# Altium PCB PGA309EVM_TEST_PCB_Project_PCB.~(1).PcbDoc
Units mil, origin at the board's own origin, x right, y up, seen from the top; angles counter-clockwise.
Board outline 6000 x 1500 mil, 2 copper layers (Top Layer, Bottom Layer), stack 62 mil thick; 95 components, 57 nets, 264 pads, 34 vias.
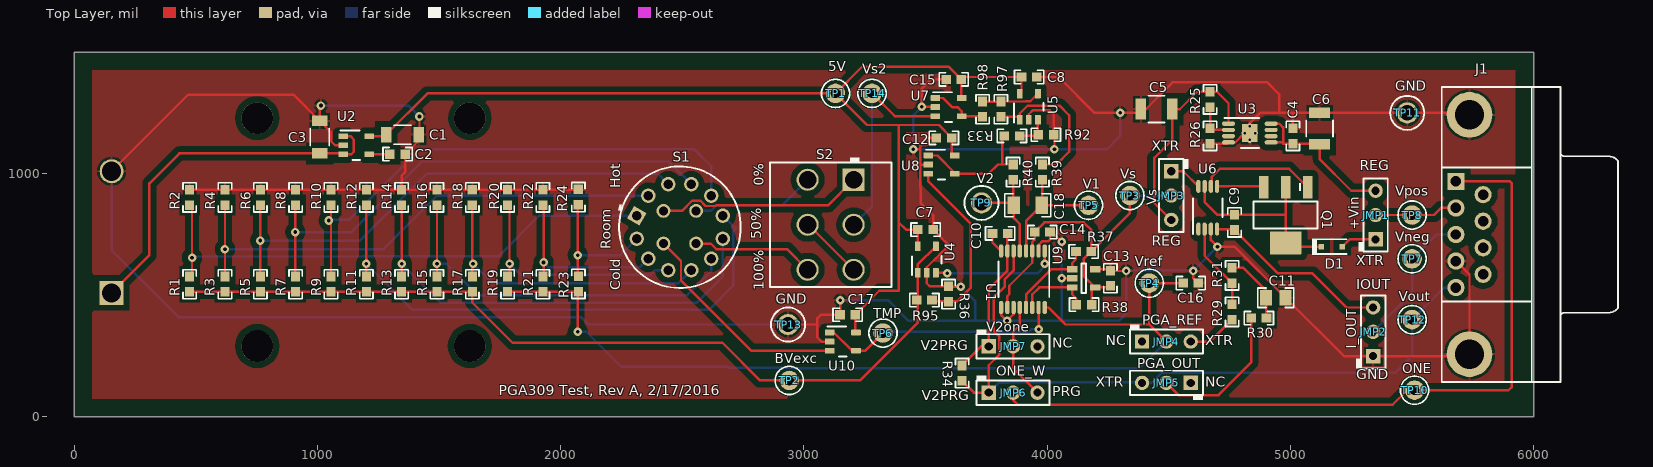
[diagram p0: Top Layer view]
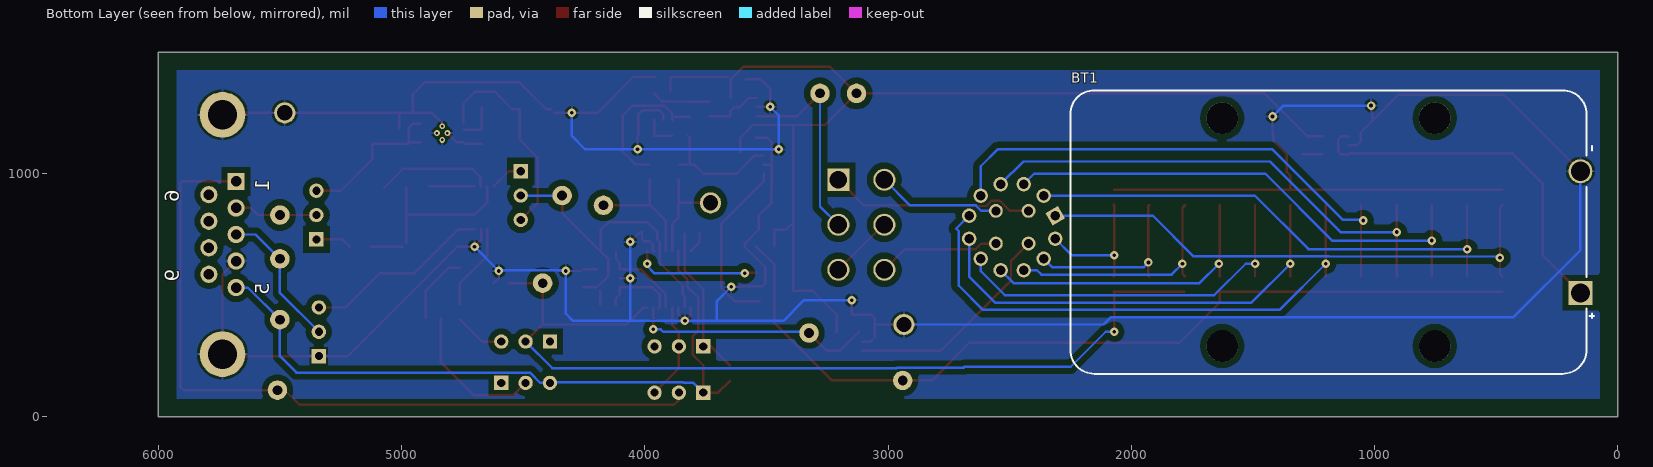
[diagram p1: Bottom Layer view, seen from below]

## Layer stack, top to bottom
Top Solder: solder mask 0.4, Solder Resist, Dk 3.5
Top Layer: signal copper 1.4
Dielectric1: core 59.2, FR-4, Dk 4.8
Bottom Layer: signal copper 1.4
Bottom Solder: solder mask 0.4, Solder Resist, Dk 3.5

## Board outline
0,0 0,1500 6000,1500 6000,0

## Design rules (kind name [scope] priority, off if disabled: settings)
AcuteAngle [All] p1: minimum=4.50000000000000E+0001 checktracksonly=FALSE
AssemblyTestPointUsage [All] p1: valid=2
BoardOutlineClearance BoardOutlineClearance_MountingHoles [OnCopper and InComponentClass('Mounting Holes')] p1: gap=40
BoardOutlineClearance BoardOutlineClearance_Poly [OnCopper and InPoly] p2: gap=25
BoardOutlineClearance [OnCopper and Not InComponentClass('Logo') and not InComponentClass('FiducialMark') and not InRegion(1000,500,4000,800)] p3: gap=75
Clearance Clearance_Keepouts [((IsTrack Or IsArc) And Not InPoly) And IsFree and IsKeepOut vs ((IsTrack Or IsArc) And Not InPoly) And IsFree and IsKeepOut] p1: gap=0
Clearance Clearance_Poly [InPolygon] p2: gap=25
Clearance [All] p3: gap=7.87
ComponentClearance ComponentClearance_MountingHoles_FiducialMarks [InComponentClass('Mounting Holes') vs InComponentClass('FiducialMark')] p1: gap=50 collisioncheckmode=3 verticalgap=10 showdistances=FALSE
ComponentClearance ComponentClearance_Shunt [InComponentClass('Header') vs InComponentClass('Shunt')] p2: gap=0 collisioncheckmode=3 verticalgap=0 showdistances=FALSE
ComponentClearance ComponentClearance_Logo [InComponentClass('Logo')] p3: gap=50 collisioncheckmode=3 verticalgap=10 showdistances=FALSE
ComponentClearance ComponentClearance_ScrewToNut [(HasFootprint('NY PMS 440 0025 PH')) vs (HasFootprint('Keystone_1902C'))] p4: gap=5 collisioncheckmode=3 verticalgap=10 showdistances=FALSE
ComponentClearance ComponentClearance_MountingHoles [InComponentClass('Mounting Holes')] p5: gap=250 collisioncheckmode=3 verticalgap=100000 showdistances=FALSE
ComponentClearance ComponentClearance_SmallPassives [HasFootprint('0201*') or HasFootprint('0402*') or HasFootprint('0508') or HasFootprint('0603*') or HasFootprint('0612') or HasFootprint('0805*') or HasFootprint('0815*') or HasFootprint('0830*') or HasFootprint('1206*') or HasFootprint('1210*') or HasFootprint('1808*') or HasFootprint('1812*') or HasFootprint('1825*') or HasFootprint('2010*') or HasFootprint('2220*') or HasFootprint('2225*') or HasFootprint('2512*') or HasFootprint('2728*') or HasFootprint('3518*') vs HasFootprint('0201*') or HasFootprint('0402*') or HasFootprint('0508') or HasFootprint('0603*') or HasFootprint('0612') or HasFootprint('0805*') or HasFootprint('0815*') or HasFootprint('0830*') or HasFootprint('1206*') or HasFootprint('1210*') or HasFootprint('1808*') or HasFootprint('1812*') or HasFootprint('1825*') or HasFootprint('2010*') or HasFootprint('2220*') or HasFootprint('2225*') or HasFootprint('2512*') or HasFootprint('2728*') or HasFootprint('3518*')] p6: gap=14.96 collisioncheckmode=3 verticalgap=10 showdistances=FALSE
ComponentClearance ComponentClearance_THtoSMT [IsThruComponent vs IsSMTComponent] p7: gap=40 collisioncheckmode=3 verticalgap=30 showdistances=FALSE
ComponentClearance ComponentClearance_THtoTH [IsThruComponent vs IsThruComponent] p8: gap=30 collisioncheckmode=3 verticalgap=30 showdistances=FALSE
ComponentClearance [All] p9: gap=30 collisioncheckmode=3 verticalgap=10 showdistances=FALSE
DiffPairsRouting [All] p1: maxlimit=100 minlimit=10 mostfreqgap=10 toplayer_minwidth=15 toplayer_maxwidth=15 toplayer_prefwidth=15 bottomlayer_minwidth=15 bottomlayer_maxwidth=15 bottomlayer_prefwidth=15 maxuncoupledlength=1000
FabricationTestPointUsage TestPointUsage [All] p1: valid=2 allowmultiple=FALSE
FabricationTestpoint Testpoint [All] p1: side=3 testpointundercomponent=TRUE minsize=40 maxsize=100 preferedsize=60 minholesize=0 maxholesize=40 preferedholesize=32 testpointgrid=1 allowsidetop=TRUE allowsidebottom=TRUE usegrid=TRUE gridtolerance=0.01
FanoutControl Fanout_LCC [IsLCC] p1: bgadir=Out bgaviamode=Centered fanoutstyle=Auto fanoutdirection=Alternating viagrid=1 // Fanout_LCC (Default Rule)
FanoutControl Fanout_BGA [IsBGA] p2: bgadir=Out bgaviamode=Centered fanoutstyle=Auto fanoutdirection=Alternating viagrid=1 // Fanout_BGA (Default Rule)
FanoutControl Fanout_Default [All] p4: bgadir=Out bgaviamode=Centered fanoutstyle=Auto fanoutdirection=Alternating viagrid=1 // Fanout_Default (Default Rule)
FanoutControl Fanout_Small [(CompPinCount < 5)] p5: bgadir=Out bgaviamode=Centered fanoutstyle=Auto fanoutdirection=OutThenIn viagrid=1 // Fanout_Small (Default Rule)
HoleSize [All] p1: absolutevalues=TRUE maxlimit=251 minlimit=7.87 maxpercent=80.000 minpercent=20.000
MinimumAnnularRing MinimumAnnularRing_ThermalPadVias [IsVia and InAnyComponent] p1: minimumring=5.91
MinimumAnnularRing [All] p2: minimumring=8
MinimumSolderMaskSliver MinimumSolderMaskSliver_Logo [InComponentClass('Logo') vs InComponentClass('Logo')] p1: minsoldermaskwidth=0.7
MinimumSolderMaskSliver [All] p2: minsoldermaskwidth=3.94
PlaneConnect [All] p1: planeconnectstyle=Relief reliefexpansion=10 reliefentries=4 reliefconductorwidth=10 reliefairgap=10
PolygonConnect [All] p1: connectstyle=Relief reliefconductorwidth=10 reliefentries=4 polygonreliefangle="90 Angle" airgapwidth=10
RoutingVias ThermalPadVias [IsVia and InAnyComponent] p1: holewidth=7.87 width=19.68 viastyle="Through Hole" minholewidth=7.87 minwidth=19.68 maxholewidth=12.99 maxwidth=23.62
RoutingVias [All] p2: holewidth=16 width=34 viastyle="Through Hole" minholewidth=7.87 minwidth=26 maxholewidth=40 maxwidth=65
SilkToBoardRegionClearance [Not ((IsComment or IsDesignator) And (Hide <> 'False')) and not InRegion(1000,500,4000,800)] p1:
SilkToSilkClearance SilkToSilkClearance_Pb-FreeLogo [(HasFootprint('Pb-Free_Overlay_Medium') OR HasFootprint('Pb-Free_Overlay_Small')) vs (HasFootprint('Pb-Free_Overlay_Medium') OR HasFootprint('Pb-Free_Overlay_Small'))] p1: silktosilkclearance=0
SilkToSilkClearance [All] p2: silktosilkclearance=4
SilkToSolderMaskClearance SilkToComponentPadClearance [IsPad and InAnycomponent] p1: minsilkscreentomaskgap=5 clearancetoexposedcopper=TRUE
SilkToSolderMaskClearance "Silk to Solder Mask Opening" [All] p2: minsilkscreentomaskgap=4 clearancetoexposedcopper=FALSE
SolderMaskExpansion [All] p1: expansion=1.97
Width [All] p1: maxlimit=100 minlimit=6 preferedwidth=10 checkconnectedcopper=TRUE
15 further rules are at their usual default settings.

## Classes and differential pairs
component class Header: JMP1 JMP2 JMP3 JMP4 JMP5 JMP6 JMP7 JMP99

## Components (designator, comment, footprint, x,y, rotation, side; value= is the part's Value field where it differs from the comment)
BT1 "1294" Keystone_1294 1190,760 r0 bottom
C1 "885012208068" 1206_190 1350,1160 r0 top
C2 "06031C103JAT2A" 0603 1330,1080 r0 top
C3 "885012208068" 1206_190 1010,1150 r90 top
C4 "C0603C104K5RACTU" 0603 5010,1155 r90 top
C5 "12103C106KAT2A" 1210_280 4450,1265 r180 top
C6 "12103C106KAT2A" 1210_280 5120,1185 r90 top
C7 "C0603C104K5RACTU" 0603 3500,770 r180 top
C8 "C0603C104K5RACTU" 0603 3925.87,1397.4 r0 top
C9 "C0603C103J5RACTU" 0603 4770,800 r270 top
C10 "06035A561JAT2A" 0603 3806.83,754.84 r0 top
C11 "08051C223JAT2A" 0805_HV 4940,490 r0 top
C12 "C0603C104K5RACTU" 0603 3575.87,1147.4 r0 top
C13 "C0603C104K5RACTU" 0603 4260.16,570 r270 top
C14 "C0603C104K5RACTU" 0603 3980,760 r180 top
C15 "C0603C104K5RACTU" 0603 3615.87,1387.4 r0 top
C16 "06033C101KAT2A" 0603 4590,550 r0 top
C17 "C0603C104K5RACTU" 0603 3180,420 r0 top
C18 "C3216C0G1E103J" 1206 3920,870 r180 top
D1 "ZHCS400TA" sod-323 5170,700 r0 top
J1 "182-009-213R171" NORCOMP_182-009-213R171 6110,750 r270 top
JMP1 "+Vin" Mill-Max_800-10-003-10-001000 5350,830 r90 top
JMP2 "I_OUT" Mill-Max_800-10-003-10-001000 5340,350 r90 top
JMP3 "Vs" Mill-Max_800-10-003-10-001000 4510,910 r270 top
JMP4 "PGA_REF" Mill-Max_800-10-003-10-001000 4490,310 r0 top
JMP5 "PGA_OUT" Mill-Max_800-10-003-10-001000 4490,140 r180 top
JMP6 "ONE_W" Mill-Max_800-10-003-10-001000 3860,100 r0 top
JMP7 "V2one" Mill-Max_800-10-003-10-001000 3860,290 r0 top
Q1 "BCP55" SOT-223 4980,830 r270 top
R1 "CRCW060328K7FKEA" 0603 475.31,545.69 r90 top
R2 "CRCW06031K05FKEA" 0603 475.24,902.39 r270 top
R3 "CRCW060340K2FKEA" 0603 620.54,545.69 r90 top
R4 "CRCW06031K50FKEA" 0603 620.47,902.39 r270 top
R5 "CRCW060371K5FKEA" 0603 765.76,545.69 r90 top
R6 "CRCW06033K74FKEA" 0603 765.7,902.39 r270 top
R7 "CRCW060310K2FKEA" 0603 910.99,545.69 r90 top
R8 "CRCW06031K91FKEA" 0603 910.92,902.39 r270 top
R9 "RT0603BRD0719K3L" 0603 1056.21,545.69 r90 top
R10 "CRCW06033K65FKEA" 0603 1056.15,902.39 r270 top
R11 "CRCW060321K5FKEA" 0603 1201.44,545.69 r90 top
R12 "CRCW06034K87FKEA" 0603 1201.38,902.39 r270 top
R13 "CRCW060311K5FKEA" 0603 1346.67,545.69 r90 top
R14 "RT0603BRD074K37L" 0603 1346.6,902.39 r270 top
R15 "CRCW060311K0FKEA" 0603 1491.89,545.69 r90 top
R16 "CRCW06034K22FKEA" 0603 1491.83,902.39 r270 top
R17 "CRCW06031K05FKEA" 0603 1637.12,545.69 r90 top
R18 "RT0603BRD0723K4L" 0603 1637.05,902.39 r270 top
R19 "CRCW060342K2FKEA" 0603 1782.35,545.69 r90 top
R20 "RT0603BRD077K96L" 0603 1782.28,902.39 r270 top
R21 "RT0603BRD076K9L" 0603 1927.57,545.69 r90 top
R22 "CRCW06031K07FKEA" 0603 1927.51,902.39 r270 top
R23 "CRCW060316K2FKEA" 0603 2072.8,546.99 r90 top
R24 "CPF0603B2K0E" 0603 2072.73,904 r270 top
R25 "CRCW0603953KFKEA" 0603 4670,1305 r90 top
R26 "RT0603BRD07291KL" 0603 4670,1155 r90 top
R29 "CRCW0603191KFKEA" 0603 4760,431.5 r90 top
R30 "CRCW060311K3FKEA" 0603 4870,405.99 r0 top
R31 "CRCW060310K0FKEA" 0603 4760,581.5 r90 top
R33 "CRCW06031K00FKEA" 0603 3855,1155 r180 top
R34 "CRCW0603100RFKEA" 0603 3650,180 r270 top
R36 "CRCW060310K0FKEA" 0603 3595,505 r270 top
R37 "CRCW060310K0FKEA" 0603 4150,680 r0 top
R38 "CRCW060310K0FKEA" 0603 4151.81,461.3 r0 top
R39 "CRCW06031K00FKEA" 0603 3980.43,1006.14 r270 top
R40 "CRCW06031K00FKEA" 0603 3860.43,1006.14 r270 top
R92 "RT0603BRD07100KL" 0603 3995,1160 r0 top
R95 "CRCW060310K0FKEA" 0603 3495,480 r180 top
R97 "CRCW06031K00FKEA" 0603 3810,1265 r270 top
R98 "RT0603BRD07100KL" 0603 3735,1265 r270 top
S1 "56P30-01-4-03N" SW_56P30-01-4-03N 2490,780 r0 top
S2 "M2024SS1G03" SW_M2024 3110,790 r270 top
TP1 "5V" Keystone5000 3130,1330 r0 top
TP2 "BVexc" Keystone5000 2940,150 r0 top
TP3 "Vs" Keystone5000 4340,910 r0 top
TP4 "Vref" Keystone5000 4420,550 r0 top
TP5 "V1" Keystone5000 4170,870 r0 top
TP6 "TMP" Keystone5004 3325,345 r0 top
TP7 "Vneg" Keystone5004 5500,650 r0 top
TP8 "Vpos" Keystone5000 5500,830 r0 top
TP9 "V2" Keystone5006 3730,880 r0 top
TP10 "ONE" Keystone5000 5510,110 r0 top
TP11 "GND" Keystone5006 5480,1250 r0 top
TP12 "Vout" Keystone5000 5500,400 r0 top
TP13 "GND" Keystone5006 2935,380 r0 top
TP14 "Vs2" Keystone5000 3280,1330 r0 top
U1 "PGA309AIPWR" PW0016A_N 3900.43,566.14 r270 top
U2 "LP2985-10DBVR" DBV0005A_N 1159.93,1116.73 r0 top
U3 "TPS7A1601DGNR" DGN0008C_N 4833,1167 r0 top
U4 "OPA333AMDBVREP" DBV0005A_N 3505.16,646.83 r90 top
U5 "OPA333AMDBVREP" DBV0005A_N 3924.45,1275.07 r90 top
U6 "XTR117AIDGKR" DGK0008A_N 4660,860 r90 top
U7 "OPA333AMDBVREP" DBV0005A_N 3594.8,1273.54 r0 top
U8 "OPA333AMDBVREP" DBV0005A_N 3565.87,1037.4 r0 top
U9 "24LC32AT-I/OT" SOT-23-5 4150.16,570 r0 top
U10 "OPA333AMDBVREP" DBV0005A_N 3160,310 r0 top

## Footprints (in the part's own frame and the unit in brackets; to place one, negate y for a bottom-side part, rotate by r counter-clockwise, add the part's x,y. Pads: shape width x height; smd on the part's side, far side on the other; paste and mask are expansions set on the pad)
0603 [mm] "0603 from SM-752 data"
  rect 1x0.95 smd: 1(-0.8,0) 2(0.8,0)
  silkscreen extent -1.52,-0.69 1.52,0.69, body extent -0.87,-0.47 0.87,0.47, height 1
0805_HV [mil] "0805 with 30mil clearance between pads"
  rect 50x63 smd: 1(-40,0) 2(40,0)
  silkscreen extent -74,-40 74,40, body extent -43,-29 43,29, height 57
1206 [mm] "1206 from SM-752 data"
  rect 1.3x1.85 smd: 1(-1.45,0) 2(1.45,0)
  silkscreen extent -2.4,-1.21 2.4,1.21, body extent -1.7,-0.9 1.7,0.9, height 1.35
1206_190 [mm] "1206_190"
  rect 1.1x1.6 smd: 1(-1.7,0) 2(1.7,0)
  silkscreen extent -0.9,-1 0.9,1, body extent -1.75,-0.95 1.75,0.95, height 1.9
1210_280 [mm] "SMD, 2-Leads, Body 3.6x2.8mm, Height 2.8mm"
  rect 1.1x2.2 smd: 1(-1.65,0) 2(1.65,0)
  silkscreen extent -0.84,-1.4 0.84,1.4, body extent -1.8,-1.4 1.8,1.4, height 2.8
DBV0005A_N [mm] "SOT23, 5-Leads, Body 2.9x1.6mm, Pitch 0.95mm, Lead Span 2.8mm, IPC Medium Density"
  rrect17% 1x0.6 smd: 1(-1.375,0.95) 2(-1.375,0) 3(-1.375,-0.95) 4(1.375,-0.95) 5(1.375,0.95)
  silkscreen extent -1.62,-1.55 0.38,1.55, body extent -1.42,-1.46 1.42,1.46, height 1.09
DGK0008A_N [mm] "TSOP, 8-Leads, Body 3x3mm, Pitch 0.65mm, IPC Medium Density"
  oval 1.35x0.45 smd: 1(-2.225,0.975) 2(-2.225,0.325) 3(-2.225,-0.325) 4(-2.225,-0.975) 5(2.225,-0.975) 6(2.225,-0.325) 7(2.225,0.325) 8(2.225,0.975)
  silkscreen extent -2.75,-1.55 0.95,1.55, body extent -2.45,-1.5 2.45,1.5, height 0.96
DGN0008C_N [mm] "TSOP, 8-Leads, Body 3x3mm, Pitch 0.65mm, Thermal Pad 1.98x1.88mm, IPC Medium Density"
  rrect100% 1.35x0.45 smd: 1(-2.225,0.975) 2(-2.225,0.325) 3(-2.225,-0.325) 4(-2.225,-0.975) 5(2.225,-0.975) 6(2.225,-0.325) 7(2.225,0.325) 8(2.225,0.975)
  rrect6% 1.6x1.918 smd: 9(0,0)
  silkscreen extent -2.65,-1.55 0.95,1.55, body extent -2.46,-1.5 2.46,1.5, height 1.1
Keystone5000 [mil] "For Keystone 500x miniature loop terminals"
  round 80 hole 40: 1(0,0)
  silkscreen extent -58,-58 58,58, body extent -49,-49 49,49, height 182
Keystone5004 [mil] "For Keystone 500x miniature loop terminals"
  round 80 hole 40: 1(0,0)
  silkscreen extent -58,-58 58,58, body extent -49,-49 49,49, height 182
Keystone5006 [mil] "Keystone Compact loops"
  round 87 hole 63: 1(0,0)
  silkscreen extent -70,-70 70,70, body extent -63,-63 62,63, height 225
Keystone_1294 [mm] "9 V Molded Battery Holder, TH"
  rect 2.5x2.5 hole 2: 1(-26.3,6.35)
  round 2.5 hole 2: 2(-26.3,-6.35)
  round 3.3 hole 3.3 unplated mask+0: MH1(-11.1,11.9) MH2(-11.1,-11.9) MH3(11.1,-11.9) MH4(11.1,11.9)
  silkscreen extent -27.75,-14.8 26.95,14.8, body extent -26.95,-14.8 26.95,14.8, height 20.3
Mill-Max_800-10-003-10-001000 [mm] "Mill-Max"
  rect 1.5x1.5 hole 0.85: 1(-2.54,0)
  round 1.5 hole 0.85: 2(0,0) 3(2.54,0)
  silkscreen extent -3.81,-1.27 3.81,1.78, body extent -3.81,-1.27 3.81,1.27, height 8.13
NORCOMP_182-009-213R171 [mm] "Connector; D Subminiature 9 Position; Right Angle"
  rect 1.8x1.8 hole 1.092: 1(-5.54,-10.92)
  round 1.8 hole 1.092: 2(-2.77,-10.92) 3(0,-10.92) 4(2.77,-10.92) 5(5.54,-10.92) 6(-4.155,-8.08) 7(-1.385,-8.08) 8(1.385,-8.08) 9(4.155,-8.08)
  round 4.76 hole 3.05: 10(-12.495,-9.5) 11(12.495,-9.5)
  silkscreen extent -15.4,-12.4 15.4,6, body extent -15.41,-12.98 15.41,6.1, height 12.55
PW0016A_N [mm] "TSOP, 16-Leads, Body 5x4.4mm, Pitch 0.65mm, IPC Medium Density"
  oval 1.4x0.45 smd: 1(-2.95,2.275) 2(-2.95,1.625) 3(-2.95,0.975) 4(-2.95,0.325) 5(-2.95,-0.325) 6(-2.95,-0.975) 7(-2.95,-1.625) 8(-2.95,-2.275) 9(2.95,-2.275) 10(2.95,-1.625) 11(2.95,-0.975) 12(2.95,-0.325) 13(2.95,0.325) 14(2.95,0.975) 15(2.95,1.625) 16(2.95,2.275)
  silkscreen extent -3.5,-2.55 1.85,2.75, body extent -3.21,-2.5 3.21,2.5, height 1
sod-323 [mm] "NXP recommended land pattern"
  rect 0.6x0.6 smd paste-0.05: 1(-1.1,0) 2(1.1,0)
  silkscreen extent -2.06,-0.86 1.53,0.86, body extent -1.3,-0.67 1.3,0.68, height 1.1
SOT-23-5 [mm] "SOT23, 5-Leads, Body 2.9x1.6mm, Pitch 0.95mm, Lead Span 2.8mm, IPC Medium Density"
  rect 1.1x0.65 smd: 1(-1.2,0.95) 2(-1.2,0) 3(-1.2,-0.95) 4(1.2,-0.95) 5(1.2,0.95)
  silkscreen extent -0.25,-1.55 0.25,1.55, body extent -1.42,-1.46 1.42,1.46, height 1.08
SOT-223 [mm] "SOT223/SC73, 4-Leads, Body 6.5x3.5mm, Pitch 2.3mm, Lead Span 7mm, IPC Medium Density"
  rrect10% 2.4x1 smd: 1(-2.9,2.3) 2(-2.9,0) 3(-2.9,-2.3)
  rrect4% 2.4x3.3 smd: 4(2.9,0)
  silkscreen extent -3.33,-3.35 1.4,3.35, body extent -3.5,-3.25 3.5,3.25, height 1.62
SW_56P30-01-4-03N [mm] "TH, 16-Leads, Dia 12.7mm"
  rect 1.5x1.5 hole 1 rot 150: 1(-4.492,1.204)
  round 1.5 hole 1: 2(-3.288,3.288) 3(-1.204,4.492) 4(1.204,4.492) 5(3.288,3.288) 6(4.492,1.204) 7(4.492,-1.204) 8(3.288,-3.288) 9(1.204,-4.492) 10(-1.204,-4.492) 11(-3.288,-3.288) 12(-4.492,-1.204)
  round 1.45 hole 0.95: C1(-1.708,1.708) C2(1.708,1.708) C3(1.708,-1.708) C4(-1.708,-1.708)
  silkscreen extent -6.47,-6.35 6.35,6.35, body extent -6.35,-6.35 6.35,6.35, height 25.45
SW_M2024 [mm] "TH, 6-Leads, Body 13x12.7 mm, Pitch 4.7mm"
  rect 2.3x2.3 hole 1.8: 1(-4.7,2.4)
  round 2.3 hole 1.8: 2(0,2.4) 3(4.7,2.4) 4(-4.7,-2.4) 5(0,-2.4) 6(4.7,-2.4)
  silkscreen extent -7,-6.35 6.5,6.35, body extent -6.5,-6.35 6.5,6.35, height 29.51

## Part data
BT1: "9 V Molded Battery Holder, TH"
C1 C3: "CAP, CERM, 4.7 µF, 25 V, +/- 10%, X7R, 1206_190"
C2: "CAP, CERM, 0.01 µF, 100 V, +/- 5%, X7R, 0603"
C4 C7 C8 C12 C13 C14 C15 C17: "CAP, CERM, 0.1 µF, 50 V, +/- 10%, X7R, 0603"
C5 C6: "CAP, CERM, 10 µF, 25 V, +/- 10%, X7R, 1210"
C9: "CAP, CERM, 0.01 µF, 50 V, +/- 5%, X7R, 0603"
C10: "CAP, CERM, 560 pF, 50 V, +/- 5%, C0G/NP0, 0603"
C11: "CAP, CERM, 0.022 µF, 100 V, +/- 5%, X7R, 0805"
C16: "CAP, CERM, 100 pF, 25 V, +/- 10%, X7R, 0603"
C18: "CAP, CERM, 0.01 µF, 25 V, +/- 5%, C0G/NP0, 1206"
D1: "Diode, Schottky, 40 V, 0.4 A, SOD-323"
J1: "CONN DB9 FEMALE R/A SOLDER TH"
JMP1 JMP2 JMP3 JMP4 JMP5 JMP6 JMP7: library part 800-10-003-10-001000, "Header, 100mil, 3x1, TH"
Q1: library part "BCP55, Fairchild Semiconductor", "Transistor, NPN, 60 V, 1.5 A, SOT-223"
R1: "RES, 28.7 k, 1%, 0.1 W, 0603"
R2 R17: "RES, 1.05 k, 1%, 0.1 W, 0603"
R3: "RES, 40.2 k, 1%, 0.1 W, 0603"
R4: "RES, 1.50 k, 1%, 0.1 W, 0603"
R5: "RES, 71.5 k, 1%, 0.1 W, 0603"
R6: "RES, 3.74 k, 1%, 0.1 W, 0603"
R7: "RES, 10.2 k, 1%, 0.1 W, 0603"
R8: "RES, 1.91 k, 1%, 0.1 W, 0603"
R9: "RES, 19.3 k, 0.1%, 0.1 W, 0603"
R10: "RES, 3.65 k, 1%, 0.1 W, 0603"
R11: "RES, 21.5 k, 1%, 0.1 W, 0603"
R12: "RES, 4.87 k, 1%, 0.1 W, 0603"
R13: "RES, 11.5 k, 1%, 0.1 W, 0603"
R14: "RES, 4.37 k, 0.1%, 0.1 W, 0603"
R15: "RES, 11.0 k, 1%, 0.1 W, 0603"
R16: "RES, 4.22 k, 1%, 0.1 W, 0603"
R18: "RES, 23.4 k, 0.1%, 0.1 W, 0603"
R19: "RES, 42.2 k, 1%, 0.1 W, 0603"
R20: "RES, 7.96 k, 0.1%, 0.1 W, 0603"
R21: "RES, 6.90 k, 0.1%, 0.1 W, 0603"
R22: "RES, 1.07 k, 1%, 0.1 W, 0603"
R23: "RES, 16.2 k, 1%, 0.1 W, 0603"
R24: "RES, 2.00 k, 0.1%, 0.063 W, 0603"
R25: "RES, 953 k, 1%, 0.1 W, 0603"
R26: "RES, 291 k, 0.1%, 0.1 W, 0603"
R29: "RES, 191 k, 1%, 0.1 W, 0603"
R30: "RES, 11.3 k, 1%, 0.1 W, 0603"
R31 R36 R37 R38 R95: "RES, 10.0 k, 1%, 0.1 W, 0603"
R33 R39 R40 R97: "RES, 1.00 k, 1%, 0.1 W, 0603"
R34: "RES, 100, 1%, 0.1 W, 0603"
R92 R98: "RES, 100 k, 0.1%, 0.1 W, 0603"
S1: "Switch, 4P3T, 4Pole, 3 Pos, 0.2 A, 115 VAC, 30 VDC, TH"
S2: "Switch, Toggle SP3T, 0.4VA, 28V, TH"
TP1 TP2 TP3 TP4 TP5 TP8 TP10 TP12 TP14: library part 5000, "Test Point, Miniature, Red, TH"
TP6 TP7: library part 5004, "Test Point, Miniature, Yellow, TH"
TP9 TP11 TP13: library part 5006, "Test Point, Compact, Black, TH"
U1: "Voltage Output Programmable Sensor Conditioner, PW0016A"
U2: "Single Output Low Noise LDO, 150 mA, Fixed 10 V Output, 2.2 to 16 V Input, with Low IQ, 5-pin SOT-23 (DBV), -40 to 125 degC, Green (RoHS & no Sb/Br)"
U3: "Single Output LDO, 100 mA, Adjustable 1.2 to 18.5 V Output, 3 to 60 V Input, with Enable and Power Good, 8-pin MSOP (DGN), -40 to 125 degC, Green (RoHS & no Sb/Br)"
U4 U5 U7 U8 U10: "Enhanced Product, Micropower CMOS Operational Amplifier Zero-Drift Series, 1.8 to 5.5 V, -55 to 125 degC, 5-pin SOT23 (DBV0005A), Green (RoHS & no Sb/Br)"
U6: "4-20mA Current-Loop Transmitter, DGK0008A"
U9: "32K I2C™ Serial EEPROM, SOT-23-5"

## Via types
v1: diameter 35, hole 15, Top Layer to Bottom Layer, 30 vias
v2: diameter 24, hole 10, Top Layer to Bottom Layer, 4 vias

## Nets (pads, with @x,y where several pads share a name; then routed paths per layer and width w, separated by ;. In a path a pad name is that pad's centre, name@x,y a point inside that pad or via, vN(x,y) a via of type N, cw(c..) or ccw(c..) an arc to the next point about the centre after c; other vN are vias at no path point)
0%: S1.C1 S2.1 | length 852.6
  Top Layer w10: S1.C1 2498.66,847.23 2540.07,888.65 2574.39,888.65 2595.98,867.05 2637.01,867.05 2639.75,869.78 3099.23,869.78 S2.1
5V: C1.1 C7.2 C8.1 C12.2 C15.2 C17.2 TP1.1 U2.5 U4.5 U5.5 U7.5 U8.5 U10.5 | length 4684.6
  Top Layer w10: U2.5 C1.1@1277.2,1154.13 ; C1.1 1453.07,1330 TP1.1 ; U10.5 3211.5,350.04 C17.2 3310,518.5 3390,518.5 3390,800 ; U4.5@3468.5,701.71 C7.2 3420,770 3390,800 ; 3607.36,1087.44 C12.2 3554.76,1200 3390,1200 ; U7.5@3647.36,1312.52 C15.2 3594.76,1440 3240,1440 TP1.1 ; C15.2@3657.36,1397.4 C8.1 U5.5@3894.37,1336.52 ; TP1.1 3260,1200 3390,1200 ; 3390,800 3390,1200
9V: BT1.1 C3.1 U2.1 U2.3 | length 1506.1
  Top Layer w10: BT1.1 310,665.43 310,960 433.07,1083.07 C3.1 U2.3@1102.06,1083.07 ; U2.3 1139.33,1079.33 1150,1090 1150,1140 1135.87,1154.13 U2.1
50%: S1.C2 S2.4 | length 511.2
  Bottom Layer w10: S1.C2 2617.19,847.23 2639.75,869.78 2910.26,869.78 S2.4
100%: S1.C3 S2.6 | length 502.9
  Top Layer w10: S1.C3 2617.19,712.77 2639.75,690.22 2930.26,690.22 S2.6
BUFTEMP: TP6.1 U1.15 U10.1 U10.4 | length 1003.5
  Top Layer w10: U10.1@3120,350 3197.4,272.6 U10.4 3252.6,272.6 TP6.1 ; U1.15 3965,449.41 v1(3965,360)
  Bottom Layer w10: TP6.1 3330,350 3925,350 3935,360 v1(3965,360)
BUFVEXC: R1.1 R3.1 R5.1 R7.1 R9.1 R11.1 R13.1 R15.1 R17.1 R95.2 TP2.1 U4.1 U4.4 | length 3611.1
  Top Layer w10: R1.1 R3.1 R5.1 R7.1 R9.1 R11.1 R13.1 R15.1 R17.1 1637.12,470.51 1802.63,305 2665,305 2820,150 TP2.1 3230,150 3468.51,388.51 3468.51,510 ; 3467.76,510.75 U4.1 3467.76,626.16 U4.4
COLD_0%: R1.2 R2.2 S1.1 | length 2196.4
  Top Layer w10: R1.2@475.24,577.25 475,577.5 485,587.5 v1(485,655) 485,860.65 475,870.65 R2.2
  Bottom Layer w10: v1@489.63,659.63 1188.05,659.63 1188.79,660.37 1213.96,660.37 1214.33,660 1333.65,660 1334.02,660.37 1359.18,660.37 1359.56,660 1478.87,660 1479.25,660.37 1504.41,660.37 1504.78,660 1627.04,660 1627.42,660.37 1652.58,660.37 1652.96,660 1745,660 1912.38,827.38 S1.1
COLD_50%: R7.2 R8.2 S1.4 | length 2088.8
  Top Layer w10: R7.2@910.92,577.25 905,583.18 910,588.18 v1(910,760) 910,859.97 905,864.97 R8.2
  Bottom Layer w10: v1(910,760) 1140,760 1430,1050 2444.21,1050 S1.4
COLD_100%: R13.2 R14.2 S1.7 | length 1880.2
  Top Layer w10: R13.2@1346.6,577.25 v1(1346.6,630) R14.2
  Bottom Layer w10: v1(1346.6,630) 1506.6,470 2560,470 2666.83,576.83 S1.7
GND: BT1.2 C1.2 C2.2 C3.2 C4.2 C5.2 C6.2 C7.1 C8.2 C11.2 C12.1 C13.1 C14.1 C15.1 C16.2 C17.1 J1.4 J1.10 J1.11 JMP2.1 R2.1 R4.1 R6.1 R8.1 R10.1 R12.1 R14.1 R16.1 R18.1 R20.1 R22.1 R24.1 R26.1 R36.1 R92.2 TP11.1 TP13.1 U1.2 U1.9 U1.11 U2.2 U3.4 U3.9 U4.2 U5.2 U6.3 U7.2 U8.2 U9.2 U9.5 U10.2 | length 16743.4
  Top Layer w10: BT1.2 469.57,1325 901.93,1325 C3.2 ; R2.1 R4.1 R6.1 R8.1 R10.1 R12.1 R14.1 ; v1@1010,1275 C3.2 ; U2.2 1073.27,1116.73 1057.48,1132.52 1057.48,1169.45 C3.2 ; C1.2 1416.93,1135.43 C2.2 1361.5,1006.5 1346.6,991.6 R14.1 ; C1.2@1420,1163.07 v1(1420,1235) ; R24.1@2071.12,933.88 R22.1 R20.1 R18.1 R16.1 R14.1 ; TP13.1 3055,380 ; U10.2 3072.63,310 3055,327.63 3055,380 ; C17.1 3070,420 3055,405 3055,380 ; C17.1@3150,421.5 v1(3150,480) ; v1(3450,1100) 3479.17,1100 ; v1(3485,1275) 3485,1350 3522.4,1387.4 C15.1 ; v1@3492.4,1275 U7.2@3539.21,1275 ; U8.2 3482.4,1037.4 3479.17,1034.17 ; C12.1 3497.4,1147.4 3479.17,1129.17 3479.17,1034.17 ; R36.1@3596.49,535 v1(3645,535) ; R36.1@3600,536.49 R36.1 3518.51,536.49 3505.16,549.84 U4.2 3505.16,615.16 3558.41,668.41 3558.53,668.41 3567.24,677.12 3567.24,677.24 3590,700 3590,711.5 C7.1 3531.5,828.5 3480,880 3480,942.16 3479.17,942.99 3479.17,1034.17 ; U1.9 3810.87,419.13 v1(3835,395) 3862.05,422.05 U1.11 ; U5.2 3924.45,1244.45 3940,1260 4010,1260 4027.36,1242.64 R92.2@4027.36,1157.4 ; C8.2 4047.6,1397.4 4195,1250 v1(4300,1250) C5.2@4370.04,1250 ; U1.2@3962.13,680 U1.2 3968.27,686.14 3968.27,709.99 3981,722.72 4004.84,722.72 4011.5,729.37 C14.1 4020,760 v1(4060,720) ; v1(4030,1100) R92.2@4030,1154.76 ; v1(4060,570) U9.2 ; U9.5 C13.1@4254.25,607.4 ; C13.1@4261.65,600 v1(4325,600) ; C5.2 4405,1265 4515,1375 4905,1375 4953.5,1326.5 4953.5,1249.96 ; v1(4600,600) 4600,571.5 C16.2 ; R26.1 4740.29,1123.5 U3.4 4772.96,1128.61 v2(4811.35,1167) ; U6.3 4672.8,727.2 v1(4700,700) 4770,700 C11.2 5220,250 JMP2.1 J1.11@5727.91,250 ; v2(4833,1194.95) 4833,1208 4874.96,1249.96 4953.5,1249.96 ; C4.2 5010,1249.96 ; J1.4 5735.98,585.04 J1.11 ; J1.10 5727.91,1250 TP11.1 C6.2 C6.2 5010,1249.96 ; 4953.5,1249.96 5010,1249.96
  Bottom Layer w10: BT1.2 154.57,685.43 429.33,410.67 2084.35,410.67 2115.02,380 TP13.1 ; v1(1015,1280) 1375,1280 v1(1420,1235) ; v1(3150,480) 3345,480 3430,395 3705,395 ; v1(3485,1275) 3450,1240 v1(3450,1100) v1(4030,1100) 4245,1100 4300,1155 v1(4300,1250) ; v1(3645,535) 3705,475 3705,395 ; v1(4060,720) v1(4060,570) 4060,395 ; v1(4700,700) 4602.87,602.87 4327.87,602.87 v1(4325,600) 4325,425 4295,395 4060,395 ; 3705,395 v1(3835,395) 4060,395
  other v2: 4833,1139.05 4854.65,1167
HOT_0%: R5.2 R6.2 S1.3 | length 2102.3
  Top Layer w10: R5.2@765.7,577.25 v1(765.7,725) R6.2
  Bottom Layer w10: v1(765.7,725) 1175,725 1450,1000 2399.45,1000 S1.3
HOT_50%: R11.2 R12.2 S1.6 | length 2240.1
  Top Layer w10: R11.2@1201.38,577.25 v1(1201.38,630) R12.2
  Bottom Layer w10: v1(1201.38,630) 1391.38,440 2610,440 2709.23,539.23 2709.23,763.45 2720,774.21 S1.6 S1.6@2666.83,823.17
HOT_100%: R17.2 R18.2 S1.9 | length 1246.2
  Top Layer w10: R17.2@1637.06,577.25 R18.2
  Bottom Layer w10: v1(1640,630) 1720,550 2484.21,550 S1.9
NetC2_1: C2.1 U2.4 | length 83.8
  Top Layer w10: U2.4@1214.74,1080 C2.1
NetC4_1: C4.1 C6.1 JMP1.3 U3.5 U3.8 | length 662.7
  Top Layer w10: U3.5 4968.61,1128.61 4970,1130 ; U3.8 4920.98,1205 4955,1205 4970,1190 4970,1130 ; C6.1@5116.54,1123.5 C4.1 4970,1123.5 4970,1130 ; C6.1 5120,1060 5250,930 JMP1.3
NetC5_1: C5.1 JMP3.3 R25.2 U3.1 | length 878.7
  Top Layer w10: JMP3.3 4440,880 4440,1065 4514.96,1139.96 C5.1 4545,1265 4616.5,1336.5 R25.2 4698.5,1336.5 4745.4,1289.6 U3.1
NetC9_1: C9.1 D1.1 Q1.2 Q1.4 U6.7 | length 784.1
  Top Layer w10: U6.7@4651.06,943.74 U6.7 4647.2,882.8 4698.5,831.5 C9.1 4978.5,831.5 4980,830 ; Q1.4 4980,830 ; Q1.2 4980,830 ; Q1.4@4995.83,700 D1.1
NetC9_2: C9.2 JMP2.3 U6.4 | length 775.2
  Top Layer w10: U6.4 4766.1,772.4 C9.2 4948.5,590 5090,590 5230,450 JMP2.3
NetC10_1: C10.1 U1.8 | length 87.3
  Top Layer w10: C10.1 3775.34,717.82 U1.8
NetC10_2: C10.2 JMP7.1 R34.1 U1.7 | length 637.2
  Top Layer w10: R34.1 3728.5,290 JMP7.1 3760,525.83 3836.46,602.29 U1.7 C10.2@3836.46,752.97
NetC11_1: C11.1 R30.2 R31.2 | length 291
  Top Layer w10: R31.2 4807.01,612.99 4900,520 C11.1 R30.2@4900,407.49
NetC18_1: C18.1 R39.2 TP5.1 U1.4 | length 508.4
  Top Layer w10: U1.4 3913.23,806.14 C18.1 TP5.1 ; C18.1@3980.43,873.35 R39.2
NetC18_2: C18.2 R40.2 TP9.1 U1.5 | length 423
  Top Layer w10: TP9.1 C18.2@3852.91,880 ; C18.2@3860.43,872.48 R40.2 ; C18.2 3862.91,817.09 3887.64,792.36 U1.5
NetD1_2: D1.2 JMP1.1 | length 149.1
  Top Layer w10: D1.2 5243.31,730 JMP1.1
NetJMP3_1: JMP3.1 U6.8 | length 137.5
  Top Layer w10: JMP3.1 4559.21,1010 U6.8
NetJMP4_3: JMP4.3 R29.1 | length 207.3
  Top Layer w10: JMP4.3 4670,310 R29.1
NetJMP5_2: JMP5.2 R30.1 | length 606.7
  Top Layer w10: JMP5.2 4540,90 4704.5,90 4838.5,224.01 R30.1
NetJMP6_3: JMP6.3 JMP7.2 U1.12 | length 402.9
  Top Layer w10: U1.12 3887.64,377.64 3860,350 JMP7.2 3860,200 JMP6.3
NetQ1_1: Q1.1 U6.6 | length 479.8
  Top Layer w10: U6.6 4676.65,951.46 4676.65,986.65 4710,1020 4994.73,1020 Q1.1
NetQ1_3: Q1.3 U6.5 | length 187.6
  Top Layer w10: U6.5 Q1.3@4886.02,947.6
NetR25_1: R25.1 R26.2 U3.2 | length 160.6
  Top Layer w10: R26.2@4670,1181.65 R26.2 R25.1 ; R26.2@4676.7,1179.8 U3.2
NetR29_2: R29.2 R31.1 U6.2 | length 356.1
  Top Layer w10: U6.2 4647.2,662.8 R31.1 R29.2
NetR33_1: R33.1 R92.1 U5.3 | length 138
  Top Layer w10: R33.1 R92.1@3960.2,1155 ; R92.1@3961.85,1156.65 U5.3
NetR33_2: R33.2 R40.1 U8.1 U8.4 | length 518.1
  Top Layer w10: U8.1 3548.46,1074.8 3620,1003.27 U8.4 3760,1000 3797.64,1037.64 3815,1037.64 ; R33.2 3815,1146.5 3815,1037.64 ; R40.1 3815,1037.64
NetR36_2: R36.2 R95.1 U8.3 | length 723.1
  Top Layer w10: U8.3 3511.73,968.27 3685,795 3685,530 3630,475 R95.1@3526.5,475
NetR37_1: R37.1 U1.13 U9.1 | length 365.1
  Top Layer w10: U1.13 3913.23,503.27 4017.36,607.4 U9.1 4102.91,632.91 4118.5,648.5 R37.1
NetR38_1: R38.1 U1.14 U9.3 | length 313.7
  Top Layer w10: U1.14@3942.68,446.14 U1.14 3938.82,503.59 3967.83,532.6 U9.3 4102.91,503.46 4120.32,486.06 R38.1
NetR39_1: R39.1 R97.2 U5.1 | length 602.2
  Top Layer w10: R97.2@3814.45,1233.57 3874.41,1233.57 ; U5.1@3885.87,1219.75 U5.1 3887.05,1247.05 3920,1280 4050,1280 4090,1240 4090,1090 4037.64,1037.64 R39.1
NetR97_1: R97.1 R98.1 U5.4 | length 240.3
  Top Layer w10: R98.1 R97.1@3814.38,1296.5 ; R97.1@3814.45,1296.57 3911.29,1296.57 3912.6,1297.87 3930.52,1297.87 U5.4
NetR98_2: R98.2 U7.1 U7.4 | length 234.3
  Top Layer w10: U7.1 3572.03,1310.95 3609.43,1273.54 3631.46,1273.54 3648.94,1256.06 U7.4 R98.2@3732.36,1236.14
NetS2_2: S2.2 TP14.1 U7.3 | length 870.8
  Top Layer w10: TP14.1 3373.86,1236.14 U7.3
  Bottom Layer w10: S2.2 3280,865.51 TP14.1
NetS2_3: S2.3 S2.5 | length 265.6
  Top Layer w10: S2.5 3019.45,790 S2.3
NetU1_1: U1.1 U4.3 | length 519.5
  Top Layer w10: U4.3 v1@3587.3,592.7 ; v1(3990,630) U1.1
  Bottom Layer w10: v1(3590,590) 3960,590 3990,620 v1(3990,630)
ONE-WIRE: J1.1 JMP6.2 TP10.1 | length 3188.4
  Top Layer w10: JMP6.2 3860,70 3880,50 5420,50 5480,110 TP10.1 5896.3,110 5910,123.7 5910,960 5901.89,968.11 J1.1
ROOM_0%: R3.2 R4.2 S1.2 | length 2124.6
  Top Layer w10: R3.2@620.47,577.25 v1(620.47,690) R4.2
  Bottom Layer w10: v1(620.47,690) 1272.71,690 1492.16,909.45 S1.2
ROOM_50%: R9.2 R10.2 S1.5 | length 2126.9
  Top Layer w10: R9.2@1056.15,577.25 1056.15,810 R10.2
  Bottom Layer w10: v1@1056.15,810 1130,810 1420,1100 2550,1100 2619.45,1030.55 S1.5
  other v1: 1047.31,807.52
ROOM_100%: R15.2 R16.2 S1.8 | length 1567.4
  Top Layer w10: R15.2@1491.83,577.25 v1(1491.83,630) R16.2
  Bottom Layer w10: v1(1491.83,630) 1530,630 1660,500 2520,500 2619.45,599.45 S1.8
T_COLD: R19.2 R20.2 S1.10 | length 982.6
  Top Layer w10: R19.2@1782.28,577.25 1780,579.53 1790,589.53 v1(1790,630) 1790,858.61 1780,868.61 R20.2
  Bottom Layer w10: v1(1790,630) 1835,585 2370,585 2388.17,603.17 S1.10
T_HOT: R23.2 R24.2 S1.12 | length 567.4
  Top Layer w10: R23.2@2072.73,578.55 2070,581.29 v1(2070,665) 2070,869.77 R24.2
  Bottom Layer w10: v1(2070,665) 2245.55,665 S1.12
T_ROOM: R21.2 R22.2 S1.11 | length 749.3
  Top Layer w10: R21.2@1927.51,577.25 1930,579.74 v1(1930,635) 1930,868.4 R22.2
  Bottom Layer w10: v1(1930,635) 1950,615 2325,615 S1.11
TEMPERATURE: S1.C4 U10.3 | length 912.2
  Top Layer w10: S1.C4 2494.98,640.56 2494.98,560.77 2783.15,272.6 U10.3
VNEG: J1.3 JMP2.2 TP7.1 | length 587.8
  Bottom Layer w10: JMP2.2 5500,510 TP7.1 5600,750 J1.3
VOUT: J1.5 JMP5.3 JMP6.1 R34.2 TP12.1 U1.6 | length 2963.4
  Top Layer w10: R34.2 3698.5,100 JMP6.1 3760,212.74 3802.4,255.14 3802.4,332.4 3780,354.8 3780,490 3826.3,536.3 3826.3,566.86 3862.05,602.6 U1.6
  Bottom Layer w10: JMP6.1 3800,140 3840.04,140 3842.44,142.4 4390,142.4 JMP5.3 4430.04,140 4472.44,182.4 5432.4,182.4 5500,250 TP12.1 5631.89,531.89 J1.5
VPOS: J1.2 JMP1.2 TP8.1 | length 342.1
  Top Layer w10: JMP1.2 TP8.1 5590,830 5619.06,859.06 J1.2
VREF: C16.1 JMP4.2 R19.1 R21.1 R23.1 TP4.1 U1.16 | length 3851.8
  Top Layer w10: R19.1 R21.1 1928.87,515.49 R23.1 2070,512.69 v1(2070,350) ; U1.16 4005,450 4075,380 4420,380 ; JMP4.2 4420,380 ; C16.1 TP4.1 4420,380
  Bottom Layer w10: v1(2070,350) 2105.6,350 2249.23,206.37 2686.22,206.37 2689.72,202.87 2961.9,202.87 2964.78,200 4380,200 JMP4.2
VS: C13.2 C14.2 JMP3.2 R37.2 R38.2 TP3.1 U1.3 U1.10 U9.4 | length 1467.3
  Top Layer w10: U1.10 3836.46,496.46 3844.17,504.17 3844.17,539.17 3938.82,633.82 U1.3 3938.82,718.82 3948.5,728.5 C14.2 3988.5,800 4150,800 4181.5,768.5 R37.2 ; R38.2 4183.31,518.5 ; C13.2@4254.25,532.6 U9.4 4150,580 4150,648.5 R37.2 ; TP3.1 4340,838.5 R37.2
  Bottom Layer w10: TP3.1 JMP3.2
pads on no net: BT1.MH1 BT1.MH2 BT1.MH3 BT1.MH4 J1.6 J1.7 J1.8 J1.9 JMP4.1 JMP5.1 JMP7.3 U3.3 U3.6 U3.7 U6.1

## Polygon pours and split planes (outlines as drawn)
GND on Top Layer "TOP_LAYER_GND_P020" (solid, remove dead copper, pour order 20): 50,1450 50,50 5950,50 5950,1450 50,1450
GND on Bottom Layer "BOTTOM_LAYER_GND_P022" (solid, remove dead copper, pour order 22): 50,1450 50,50 5950,50 5950,1450 50,1450

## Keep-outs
Keep-Out Layer:
  text ".Layer_Name" at 577,-858.49 h60

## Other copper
Top Layer:
  text ".Layer_Name" at 577,-858.49 h60
Bottom Layer:
  text ".Layer_Name" at 577,-858.49 h60

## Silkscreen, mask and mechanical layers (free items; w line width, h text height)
Top Overlay:
  text "XTR" at 4430,1080 h72.83
  text "REG" at 5285,1000 h72.83
  text "0%" at 2850,950 h72.83 r90
  text "Hot" at 2260,940 h72.83 r90
  text "50%" at 2840,730 h72.83 r90
  text "Room" at 2220,690 h72.83 r90
  text "REG" at 4430,690 h72.83
  text "XTR" at 5270,610 h72.83
  text "Cold" at 2260,520 h72.83 r90
  text "100%" at 2850,520 h72.83 r90
  text "IOUT" at 5270,510 h72.83
  text "NC" at 4240,280 h72.83
  text "XTR" at 4650,280 h72.83
  text "NC" at 4020,270 h72.83
  text "V2PRG" at 3480,260 h72.83
  text "GND" at 5270,140 h72.83
  text "XTR" at 4200,110 h72.83
  text "NC" at 4650,110 h72.83
  text "PGA309 Test, Rev A, 2/17/2016" at 1745,75 h72.83
  text "PRG" at 4020,70 h72.83
  text "V2PRG" at 3485,55 h72.83
  text ".Layer_Name" at 577,-858.49 h60
Bottom Overlay:
  text ".Layer_Name" at 577,-858.49 h60
Top Paste:
  text ".Layer_Name" at 577,-858.49 h60
Bottom Paste:
  text ".Layer_Name" at 577,-858.49 h60
Top Solder:
  text ".Layer_Name" at 577,-858.49 h60
  text ".Layer_Name" at 577,-858.49 h60
Bottom Solder:
  text ".Layer_Name" at 577,-858.49 h60
Drill Guide:
  text ".Layer_Name" at 577,-858.49 h60
M1 Board Outline:
  the board outline again, w10
  text ".Layer_Name" at 577,-858.49 h60
M2 Board Dimensions:
  rectangle: 0,-275 125,-150
  rectangle: 125,-400 500,-275
  lines w7: 0,-275 1000,-275 ; 125,-400 125,-150 ; 250,-400 250,-150 ; 500,-400 500,-150 ; 750,-400 750,-150 ; 0,-400 1000,-400 1000,-150 0,-150 0,-400
  lines w10: -220,60 -200,0 ; -220,1440 -200,1500 ; -210,0 -190,0 ; -210,1500 -190,1500 ; -200,474.08 -200,0 ; -200,1025.92 -200,1500 ; -180,60 -200,0 ; -180,1440 -200,1500 ; 0,1790 0,1810 ; 60,1780 0,1800 ; 60,1820 0,1800 ; 2719.09,1800 0,1800 ; 3280.91,1800 6000,1800 ; 5940,1780 6000,1800 ; 5940,1820 6000,1800 ; 6000,1790 6000,1810
  text "6000 (mil)" at 2729.09,1764.01 h60
  text "1500 (mil)" at -164.01,484.08 h60 r90
  text ".Layer_Name" at 577,-858.49 h60
M3 3D STEP Top:
  text ".Layer_Name" at 577,-858.49 h60
M4 3D STEP Bottom:
  text ".Layer_Name" at 577,-858.49 h60
M5 Assembly Top:
  lines w10: -292,-930.17 6308,-930.17 ; -292,-726.83 6310,-726.83 ; -292,-523.5 -292,-1133.5 3713,-1133.5 6310,-1133.5 6310,-523.5 -291.5,-523.5 -291.5,-1133.5 1284,-1133.5 ; 2173,-1133.5 2173,-523.5 ; 3440,-726.83 3440,-523.5 ; 4280,-726.83 4280,-523.5 ; 4902,-1140 4902,-937.17
  text "COMPONENTS MARKED 'DNP' SHOULD NOT BE POPULATED." at 1153.5,-318.5 h60
  text "ASSEMBLY VARIANT:" at 1153,-434 h60
  text ".VariantName" at 2189,-434 h60
  text "PCB VIEWED FROM TOP SIDE" at -228.5,-655.67 h60
  text "BOARD #:" at 2248,-655.67 h60
  text ".PRJ_Number" at 2793.5,-655.67 h60
  text "REV:" at 3638,-655.67 h60
  text ".PCB_Rev" at 3929.5,-655.67 h60
  text "SVN REV:" at 4476,-655.67 h60
  text ".VersionControl_RevNumber" at 4982,-655.67 h60
  text "TID #:" at 2248,-859 h60
  text ".TID" at 2793.5,-859 h60
  text "PLOT NAME =" at -228.5,-1064.34 h60
  text ".plot_File_Name" at 577,-1064.34 h60
  text "GENERATED    :" at 2250,-1064.34 h60
  text ".Print_Date" at 3119.5,-1064.34 h60
  text ".Print_Time" at 3848.5,-1064.34 h60
  text "TEXAS INSTRUMENTS" at 5113,-1064.34 h60
M6 Assembly Bottom:
  lines w10: -292.5,-727.33 6309.5,-727.33 ; -290.5,-930.67 6309.5,-930.67 ; 1115.5,-1140.5 1115.5,-937.67 ; 1737.5,-727.33 1737.5,-524 ; 2577.5,-727.33 2577.5,-524 ; 3844.5,-1134 3844.5,-524 ; 4733.5,-1134 6309,-1134 6309,-524 -292.5,-524 -292.5,-1134 2304.5,-1134 6309.5,-1134 6309.5,-524
  text "COMPONENTS MARKED 'DNP' SHOULD NOT BE POPULATED." at 6102,-318 h60
  text ".VariantName" at 5058,-434 h60
  text "ASSEMBLY VARIANT:" at 6097,-434 h60
  text ".VersionControl_RevNumber" at 1035.5,-656.17 h60
  text "SVN REV:" at 1541.5,-656.17 h60
  text ".PCB_Rev" at 2088,-656.17 h60
  text "REV:" at 2379.5,-656.17 h60
  text ".PRJ_Number" at 3224,-656.17 h60
  text "BOARD #:" at 3769.5,-656.17 h60
  text "PCB VIEWED FROM BOTTOM SIDE" at 6246,-656.17 h60
  text ".TID" at 3224,-859.5 h60
  text "TID #:" at 3769.5,-859.5 h60
  text "TEXAS INSTRUMENTS" at 904.5,-1064.84 h60
  text ".Print_Time" at 2169,-1064.84 h60
  text ".Print_Date" at 2898,-1064.84 h60
  text "GENERATED    :" at 3767.5,-1064.84 h60
  text ".plot_File_Name" at 5440.5,-1064.84 h60
  text "PLOT NAME =" at 6246,-1064.84 h60
M9 Title Sheet:
  drawing of 57 lines, arcs and shapes, not listed
  text "1" at 739.84,8036.5 h70
  text "2" at 3235.5,8036.5 h70
  text "3" at 5724.84,8036.5 h70
  text "4" at 8231.51,8036.5 h70
  text "5" at 10730.5,8036.5 h70
  text "6" at 13235.5,8036.5 h70
  text "A" at -416.5,6893.5 h70
  text "A" at 14383.5,6893.5 h70
  text "B" at -416.5,4513.5 h70
  text "B" at 14383.5,4513.5 h70
  text "C" at -416.5,2138.5 h70
  text "C" at 14383.5,2138.5 h70
  text "PROJECT TITLE:" at 11343.5,277.5 h45
  text ".PRJ_Title" at 11393.5,144.17 h70
  text "DESIGNED FOR:" at 11343.5,-23.5 h45
  text ".PRJ_Customer" at 11393.5,-163.5 h70
  text "D" at -416.5,-231.5 h70
  text "D" at 14383.5,-231.5 h70
  text "FILE NAME:" at 11343.5,-323.5 h45
  text ".PCB_File_Name_No_Path" at 11393.5,-443.5 h70
  text "Texas Instruments (TI) and/or its licensors do not warrant the accuracy or completeness of this specification" at 6374,-605.34 h45
  text "ENGINEER:" at 11343.5,-613.5 h45
  text "LAYOUT BY:" at 12848.5,-613.5 h45
  text "or any information contained therein. TI and/or its licensors do not warrant that this design will meet" at 6329.01,-718 h45
  text ".PRJ_Engineer" at 11393.5,-768.49 h70
  text ".PCB_Layout" at 12899,-768.49 h70
  text "the specifications, will be suitable for your application or fit for any particular purpose, or will operate in" at 6329.01,-830.67 h45
  text ".Layer_Name" at 577,-858.49 h60
  text "ALTIUM DESIGNER VERSION:" at 12848.5,-923.5 h45
  text "an implementation. TI and/or its licensors do not warrant that the design is production worthy. You should" at 6329.01,-943.33 h45
  text "completely validate and test your design implementation to confirm the system functionality for your application." at 6374,-1056 h45
  text ".print_Scale" at 11393.5,-1056.83 h70
  text ".Application_BuildNumber" at 12899,-1056.83 h70
  text "1" at 739.84,-1263.5 h70
  text "2" at 3235.5,-1263.5 h70
  text "3" at 5724.84,-1263.5 h70
  text "4" at 8231.51,-1263.5 h70
  text "5" at 10730.5,-1263.5 h70
  text "6" at 13235.5,-1263.5 h70
M10 Fab Notes:
  drawing of 173 lines, arcs and shapes, not listed
  text "DESIGN INFORMATION" at 12378.02,6201 h60
  text "MIN. TRACK WIDTH:" at 11733.46,6021 h60
  text "8" at 12829.7,6021 h60
  text "MIL" at 12984.46,6021 h60
  text "MIN. CLEARANCE:" at 11733.46,5889 h60
  text "0.2" at 12769.7,5889 h60
  text "mm" at 12984.46,5889 h60
  text "MIN. VIA PAD SIZE:" at 11733.46,5757 h60
  text "24" at 12799.71,5757 h60
  text "MIL" at 12984.46,5757 h60
  text "0.05mm (2MIL)" at 12428.46,5615.29 h60
  text "MINIMUM ANNULAR RING" at 11404.23,5611 h60
  text "EXTERNAL" at 13136.46,5611 h60
  text "PER" at 11604.23,5493 h60
  text "IPC-D-275 CLASS 2 LEVEL C" at 11824.23,5493 h60
  text "MIL, HOLES" at 13312.46,5380.71 h60
  text "+/-" at 12920,5380 h60
  text "+/-" at 13774,5380 h60
  text "REGISTRATION TOLERANCES:" at 11404.23,5375 h60
  text "METAL" at 12604,5375 h60
  text "5" at 13180.2,5375 h60
  text "3" at 14013.2,5375 h60
  text "MIL" at 14129.46,5375 h60
  text "+/-" at 13774,5262 h60
  text "HOLE SIZE TOLERANCE (UNLESS OTHERWISE SPECIFIED):" at 11404.23,5257 h60
  text "3" at 14013.2,5257 h60
  text "MIL" at 14129.46,5257 h60
  text "MATERIAL:" at 11329.46,5047.54 h60
  text "FR-4 High Tg" at 12315.9,4907.21 h60
  text "FR-408" at 11750.46,4898.64 h60
  text "OTHER" at 13238.46,4898.64 h60
  text "X" at 12161,4895 h60
  text "62 MIL (1.6mm) +/-10%" at 12070.56,4735.92 h60
  text "THICKNESS:" at 11404.23,4731.64 h60
  text "X" at 11942.4,4731.64 h60
  text "OTHER" at 13355.46,4731.64 h60
  text "TOLERANCE:" at 11404.23,4573.64 h60
  text "X" at 12243.53,4573.64 h60
  text "ANSI IPC-6012 TYPE 3 CLASS 2" at 12430.48,4573.64 h60
  text "OTHER +/-" at 12430.46,4417.64 h60
  text "BOW & TWIST:" at 11404.23,4260.64 h60
  text "X" at 12243.53,4260.64 h60
  text "ANSI IPC-6012 TYPE 3 CLASS 2" at 12430.48,4260.64 h60
  text "OTHER +/-" at 12430.46,4102.13 h60
  text "DRILLING:" at 11329.46,3963.64 h60
  text "REFERENCE:" at 11404.23,3846.64 h60
  text "X" at 12052.46,3846.64 h60
  text "AS SHOWN" at 12239.46,3846.64 h60
  text "X" at 12953.46,3846.64 h60
  text "NC_DRILL FILES" at 13090.46,3846.64 h60
  text "PTH MIN COPPER THICKNESS:" at 11404.23,3688.64 h60
  text "X" at 12754.46,3688.64 h60
  text "1MIL" at 12891.46,3688.64 h60
  text "OTHER" at 13388.46,3688.64 h60
  text "BOARD FINISH:" at 11329.46,3529.64 h60
  text "SILKSCREEN:" at 11484.68,3411.64 h60
  text "X" at 12433.46,3411.64 h60
  text "TOP" at 12559.46,3411.64 h60
  text "X" at 12943.46,3411.64 h60
  text "BOTTOM" at 13070.46,3411.64 h60
  text "SILKSCREEN COLOR:" at 11484.68,3244.64 h60
  text "X" at 12432.42,3244.64 h60
  text "WHITE" at 12559.46,3244.64 h60
  text "OTHER" at 13070.46,3244.64 h60
  text "X" at 12563.42,3085.44 h60
  text "GREEN" at 12690.46,3085.44 h60
  text "OTHER" at 13308.46,3085.44 h60
  text "SOLDER RESIST COLOR:" at 11484.68,3074.64 h60
  text "X" at 12563.42,2915.44 h60
  text "MATTE" at 12690.46,2915.44 h60
  text "SEMI-GLOSS" at 13308,2914.8 h60
  text "IMMERSION GOLD (ENIG)" at 12390.46,2726.92 h60
  text "ENEPIG" at 13728,2723.64 h60
  text "SURFACE FINISH:" at 11329.46,2722.64 h60
  text "X" at 12203.51,2722.64 h60
  text "IMM. TIN/SILVER OR EQUIV" at 11659,2565.64 h60
  text "OTHER" at 13090.46,2565.64 h60
  text "ARRAY/PANEL:" at 11329.46,2386.64 h60
  text "CUT AND TRIM PER M1 BOARD OUTLINE" at 12390.46,2382.35 h60
  text "N.C. ROUTE" at 12390.46,2230.64 h60
  text "X" at 13069.46,2230.64 h60
  text "V. SCORE" at 13256.46,2230.64 h60
  text "CERTIFICATION:" at 11329.46,2093.64 h60
  text "MATERIALS AND WORKMANSHIP FOR ALL PCBS" at 12054.46,2093.64 h60
  text "TO MEET OR EXCEED THE REQUIREMENTS OF:" at 12054.46,1995.64 h60
  text "X" at 11680.96,1859.13 h60
  text "ANSI IPC-A-600F CLASS ->" at 11819.96,1859.13 h60
  text "X" at 13459.02,1859.13 h60
  text "2" at 13577.96,1859.14 h60
  text "1" at 13262.96,1857.64 h60
  text "3" at 13931.96,1857.64 h60
  text "X" at 12495.02,1699.64 h60
  text "RoHS" at 12631.96,1699.64 h60
  text "OTHER" at 13276.36,1699.64 h60
  text "PER ORDER" at 13673.42,1699.64 h60
  text "ALL BOARDS MUST MEET OR EXCEED UL94-V0 REQUIREMENTS." at 11357,1534 h60
  text "PCB MUST BEAR THE UL94V-0 UL REGISTERED MATERIAL ID NUMBER" at 11357,1414 h60
  text "ADDITIONAL REQUIREMENTS:" at 11329.46,1240.64 h60
  text "MICROSECTION:" at 11404.23,1125.64 h60
  text "YES" at 12309.96,1125.64 h60
  text "REQUIRED" at 13171.46,969.49 h60
  text "BARE BOARD ELEC. TEST:" at 11404.23,966.64 h60
  text "NONE" at 12709.96,966.64 h60
  text "X" at 13044.46,966.64 h60
  text "PER ORDER" at 13763.46,966.64 h60
  text ".Layer_Name" at 577,-858.49 h60
M11 Gerber Information:
  lines w10: -292,-930.17 6308,-930.17 ; -292,-726.83 6310,-726.83 ; -292,-523.5 -292,-1133.5 3713,-1133.5 6310,-1133.5 6310,-523.5 -291.5,-523.5 -291.5,-1133.5 1284,-1133.5 ; 2173,-1133.5 2173,-523.5 ; 3440,-726.83 3440,-523.5 ; 4280,-726.83 4280,-523.5 ; 4902,-1140 4902,-937.17
  text "ALL ARTWORK VIEWED FROM TOP SIDE" at -228.5,-655.67 h60
  text "BOARD #:" at 2248,-655.67 h60
  text ".PRJ_Number" at 2793.5,-655.67 h60
  text "REV:" at 3638,-655.67 h60
  text ".PCB_Rev" at 3929.5,-655.67 h60
  text "SVN REV:" at 4476,-655.67 h60
  text ".VersionControl_RevNumber" at 4982,-655.67 h60
  text "LAYER NAME =" at -228.5,-858.49 h60
  text "TID #:" at 2248,-859 h60
  text ".TID" at 2793.5,-859 h60
  text "PLOT NAME =" at -228.5,-1064.34 h60
  text ".plot_File_Name" at 577,-1064.34 h60
  text "GENERATED    :" at 2250,-1064.34 h60
  text ".Print_Date" at 3119.5,-1064.34 h60
  text ".Print_Time" at 3848.5,-1064.34 h60
  text "TEXAS INSTRUMENTS" at 5113,-1064.34 h60
M12 Stackup:
  drawing of 191 lines, arcs and shapes, not listed
  text "Layer" at 9790.34,7830 h60
  text "Name" at 10200.26,7830 h60
  text "Material" at 11130,7830 h60
  text "Thickness" at 11989.77,7830 h60
  text "Constant" at 12639.6,7830 h60
  text "Board Layer Stack" at 13209.46,7830 h60
  text "1" at 9790.34,7710 h60
  text "Top Overlay" at 10200.26,7710 h60
  text "2" at 9790.34,7590 h60
  text "Top Solder" at 10200.26,7590 h60
  text "Solder Resist" at 11130,7590 h60
  text "0.40mil" at 11989.77,7590 h60
  text "3.5" at 12639.6,7590 h60
  text "3" at 9790.34,7470 h60
  text "Top Layer" at 10200.26,7470 h60
  text "Copper" at 11130,7470 h60
  text "1.40mil" at 11989.77,7470 h60
  text "4" at 9790.34,7350 h60
  text "Dielectric1" at 10200.26,7350 h60
  text "FR-4" at 11130,7350 h60
  text "59.20mil" at 11989.77,7350 h60
  text "4.8" at 12639.6,7350 h60
  text "5" at 9790.34,7230 h60
  text "Bottom Layer" at 10200.26,7230 h60
  text "Copper" at 11130,7230 h60
  text "1.40mil" at 11989.77,7230 h60
  text "6" at 9790.34,7110 h60
  text "Bottom Solder" at 10200.26,7110 h60
  text "Solder Resist" at 11130,7110 h60
  text "0.40mil" at 11989.77,7110 h60
  text "3.5" at 12639.6,7110 h60
  text "7" at 9790.34,6990 h60
  text "Bottom Overlay" at 10200.26,6990 h60
  text ".Layer_Name" at 577,-858.49 h60
M13 Component Bodies Top:
  text ".Layer_Name" at 577,-858.49 h60
M14 Component Bodies Bottom:
  text ".Layer_Name" at 577,-858.49 h60
M15 Courtyards Top:
  text ".Layer_Name" at 577,-858.49 h60
M16 Courtyards Bottom:
  text ".Layer_Name" at 577,-858.49 h60
Drill Drawing:
  text ".Layer_Name" at 577,-858.49 h60
M17 Embedded Cavity:
  text ".Layer_Name" at 577,-858.49 h60
M18 Embedded Assembly:
  text ".Layer_Name" at 577,-858.49 h60
M19 Embedded Keepout:
  text ".Layer_Name" at 577,-858.49 h60

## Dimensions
0,-400 to 1000,-400 on M2 Board Dimensions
